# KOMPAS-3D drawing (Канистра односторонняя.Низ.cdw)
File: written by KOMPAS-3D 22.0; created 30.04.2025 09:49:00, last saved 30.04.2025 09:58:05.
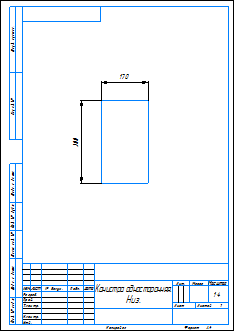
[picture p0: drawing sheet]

Sheet 1: A4, portrait

Document properties: Автор: Admin; Наименование: Канистра односторонняя. Низ; Полное имя файла: D:\28.11.2016\3D модели\Абилимпикс\2025\Канистра односторонняя\Канистра односторонняя.Низ.cdw

Title block, sheet 1: Наименование: Канистра односторонняя. / Низ.; scale: 1:4; Количество листов документа: 1; Форматы листов документа: A4; stored path: D:\28.11.2016\3D модели\Абилимпикс\2025\Канистра односторонняя\Канистра односторонняя.Зад.cdw

Dimensions and other numbers on the sheet: 300; 170; 1:4; 1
